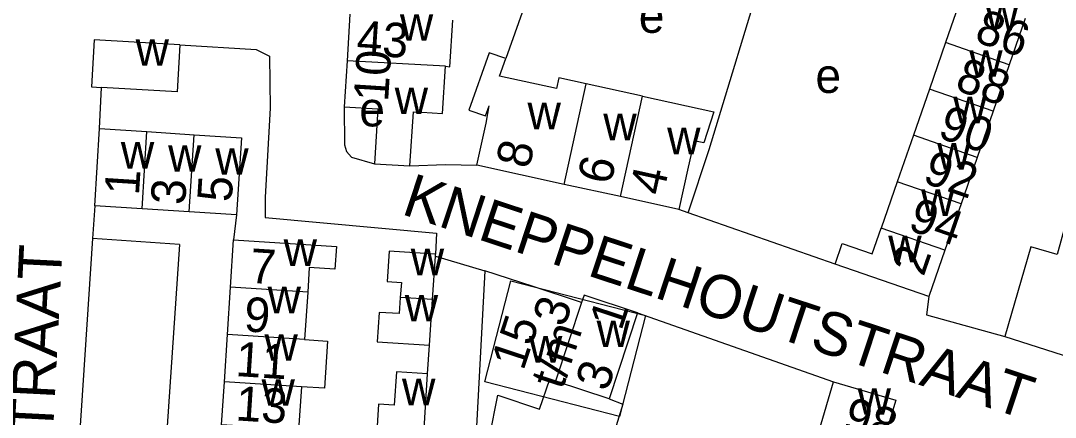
# Model space of a CAD drawing. Extents: x 159700 to 161346, y 381730 to 382922.
# Drawn here: x 160528.5 to 160648.4, y 382093.7 to 382139.7 of the extents above; entities that cross this region are included whole.
import ezdxf

# ---------------------------------------------------------------- set-up
doc = ezdxf.new("R2010")
doc.units = 0
for name, color, linetype in [('BLT_Basislijn', 7, 'Continuous'), ('BLT_Bebouwing', 7, 'Continuous'), ('BLT_Centroide', 7, 'Continuous'), ('BLT_Huisnummer', 7, 'Continuous'), ('BLT_Huisnummer_ tussenligend', 7, 'Continuous'), ('BLT_Huisnummer_zonder_bebouwing', 7, 'Continuous'), ('BLT_Onderverdeling_panden', 7, 'Continuous'), ('BLT_Plantopo', 7, 'Continuous'), ('BLT_Straatnaam', 7, 'Continuous')]:
    doc.layers.add(name, color=color, linetype=linetype)

msp = doc.modelspace()

# ---------------------------------------------------------------- linework, layer by layer
at = {"layer": 'BLT_Basislijn'}
for p, q in [((160591.41, 382154.25), (160584.69, 382135.26)), ((160537.62, 382127.15), (160537.83, 382131.93)), ((160537.05, 382118.21), (160536.8, 382114.41)), ((160605.81, 382117.41), (160604.74, 382117.78)), ((160622.85, 382111.45), (160605.81, 382117.41)), ((160553.47, 382117.17), (160553.15, 382114.28)), ((160536.8, 382114.41), (160535.16, 382089.9)), ((160546.87, 382113.74), (160536.8, 382114.41)), ((160546.87, 382113.74), (160545.23, 382089.23)), ((160576.53, 382112.36), (160582.26, 382110.69)), ((160599.95, 382105.8), (160622.66, 382097.82)), ((160642.5, 382103.07), (160651.59, 382100.14)), ((160575.62, 382098.75), (160575.85, 382102.04))]:
    msp.add_line(p, q, dxfattribs=at)
for points in [[(160681.91, 382220.18), (160679.43, 382214.59), (160683.36, 382212.77), (160677.31, 382195.82), (160674.59, 382196.42), (160665.51, 382171.9), (160668.53, 382170.99), (160661.57, 382151.91), (160658.85, 382152.82), (160649.77, 382125.87), (160651.89, 382124.66), (160648.56, 382112.55), (160645.53, 382113.46), (160642.5, 382103.07)], [(160605.81, 382117.41), (160608.25, 382124.72), (160614.86, 382146.46)], [(160546.92, 382136.85), (160555.77, 382136.31), (160557.32, 382135.53), (160557.37, 382129.52), (160556.8, 382119.22), (160556.8, 382116.86), (160576.67, 382115.05), (160576.54, 382112.62)], [(160565.95, 382129.69), (160566.01, 382125.26), (160566.22, 382124.5), (160566.8, 382123.83), (160569.46, 382123.09)], [(160573.57, 382122.83), (160577.69, 382122.99), (160581.33, 382122.91)], [(160633.7, 382107.69), (160633.43, 382105.59), (160642.5, 382103.07)], [(160596.66, 382095.83), (160598.24, 382095.24), (160592.76, 382077.43)]]:
    msp.add_lwpolyline(points, dxfattribs=at)
at = {"layer": 'BLT_Bebouwing'}
for p, q in [((160637.49, 382142.49), (160635.63, 382137.12)), ((160566.63, 382140.42), (160566.29, 382135.02)), ((160644.87, 382139.93), (160643.01, 382134.56)), ((160635.63, 382137.12), (160633.77, 382131.74)), ((160566.29, 382135.02), (160565.95, 382129.69)), ((160643.01, 382134.56), (160641.15, 382129.19)), ((160641.15, 382129.19), (160639.29, 382123.81)), ((160537.05, 382118.21), (160537.62, 382127.15)), ((160537.62, 382127.15), (160543.1, 382126.8)), ((160543.1, 382126.8), (160548.57, 382126.45)), ((160639.29, 382123.81), (160637.43, 382118.44)), ((160569.46, 382123.09), (160573.57, 382122.83)), ((160591.44, 382120.69), (160581.33, 382122.91)), ((160630.05, 382120.99), (160628.18, 382115.62)), ((160597.96, 382119.27), (160591.44, 382120.69)), ((160604.74, 382117.78), (160597.96, 382119.27)), ((160542.53, 382117.86), (160537.05, 382118.21)), ((160548, 382117.51), (160542.53, 382117.86)), ((160553.47, 382117.17), (160548, 382117.51)), ((160637.43, 382118.44), (160635.56, 382113.06)), ((160552.79, 382108.79), (160553.15, 382114.28)), ((160576.53, 382112.36), (160576.54, 382112.62)), ((160635.56, 382113.06), (160633.7, 382107.69)), ((160576.2, 382107.34), (160576.53, 382112.36)), ((160633.7, 382107.69), (160622.85, 382111.45)), ((160587.86, 382108.84), (160582.26, 382110.69)), ((160552.43, 382103.3), (160552.79, 382108.79)), ((160561.73, 382108.2), (160561.37, 382102.71)), ((160593.47, 382106.99), (160587.86, 382108.84)), ((160575.85, 382102.04), (160576.2, 382107.34)), ((160552.07, 382097.8), (160552.43, 382103.3)), ((160575.14, 382091.07), (160575.62, 382098.75)), ((160561.01, 382097.22), (160560.68, 382092.24)), ((160590.46, 382097.87), (160589.77, 382098.1)), ((160596.66, 382095.83), (160590.46, 382097.87)), ((160621.03, 382092.28), (160622.66, 382097.82))]:
    msp.add_line(p, q, dxfattribs=at)
for points in [[(160577.68, 382134.39), (160578.19, 382134.3), (160578.54, 382139.7)], [(160546.92, 382136.85), (160536.99, 382137.45), (160536.66, 382132), (160537.83, 382131.93)], [(160546.92, 382136.85), (160546.59, 382131.4), (160537.83, 382131.93)], [(160584.69, 382135.26), (160582.76, 382135.95), (160580.41, 382129.3), (160582.34, 382128.62), (160582.76, 382129.8)], [(160573.57, 382122.83), (160573.97, 382129.11), (160574.96, 382129.05), (160577.33, 382128.89), (160577.68, 382134.39)], [(160593.99, 382132.33), (160590.83, 382133.03), (160590.55, 382131.79), (160583.97, 382133.22), (160584.69, 382135.26)], [(160600.54, 382130.91), (160593.99, 382132.33)], [(160633.77, 382131.74), (160631.92, 382126.41)], [(160600.54, 382130.91), (160608.79, 382129.1), (160607.63, 382125.49), (160606.49, 382125.74), (160606.3, 382124.87), (160605.81, 382122.67), (160604.74, 382117.78)], [(160565.95, 382129.69), (160569.87, 382129.44), (160569.46, 382123.09)], [(160581.33, 382122.91), (160582.4, 382127.79), (160582.76, 382129.8)], [(160548.57, 382126.45), (160554.04, 382126.1), (160553.47, 382117.17)], [(160631.92, 382126.41), (160630.05, 382120.99)], [(160622.85, 382111.45), (160623.67, 382113.83), (160627.15, 382112.63), (160628.18, 382115.62)], [(160553.15, 382114.28), (160562.08, 382113.69), (160565.06, 382113.5), (160564.89, 382110.86), (160561.91, 382111.06), (160561.73, 382108.2)], [(160576.54, 382112.62), (160571.16, 382112.97), (160570.92, 382109.42), (160572.58, 382109.31), (160572.46, 382107.57)], [(160582.26, 382110.69), (160581.26, 382091.9), (160582.79, 382091.39), (160583.76, 382096.25), (160588.6, 382094.66), (160589.77, 382098.1)], [(160599.95, 382105.8), (160593.75, 382107.85), (160593.47, 382106.99)], [(160572.46, 382107.57), (160572.34, 382105.71), (160570, 382105.86), (160569.77, 382102.44), (160575.85, 382102.04)], [(160599.95, 382105.8), (160597.74, 382099.11), (160596.66, 382095.83)], [(160561.37, 382102.71), (160564.04, 382102.54), (160563.66, 382097.06), (160561.01, 382097.22)], [(160575.62, 382098.75), (160572, 382098.98), (160571.76, 382095.11), (160569.93, 382095.23), (160569.69, 382091.45), (160573.01, 382091.24)], [(160553.01, 382092.74), (160551.75, 382092.82), (160552.07, 382097.8)], [(160622.66, 382097.82), (160629.86, 382095.69), (160628.23, 382090.15)]]:
    msp.add_lwpolyline(points, dxfattribs=at)
at = {"layer": 'BLT_Onderverdeling_panden'}
for p, q in [((160643.01, 382134.56), (160635.63, 382137.12)), ((160577.68, 382134.39), (160566.29, 382135.02)), ((160591.44, 382120.69), (160593.99, 382132.33)), ((160641.15, 382129.19), (160633.77, 382131.74)), ((160597.96, 382119.27), (160600.54, 382130.91)), ((160542.53, 382117.86), (160543.1, 382126.8)), ((160548, 382117.51), (160548.57, 382126.45)), ((160639.29, 382123.81), (160631.92, 382126.41)), ((160637.43, 382118.44), (160630.05, 382120.99)), ((160635.56, 382113.06), (160628.18, 382115.62)), ((160561.73, 382108.2), (160552.79, 382108.79)), ((160576.2, 382107.34), (160572.46, 382107.57)), ((160593.47, 382106.99), (160590.46, 382097.87)), ((160561.37, 382102.71), (160552.43, 382103.3)), ((160561.01, 382097.22), (160552.07, 382097.8))]:
    msp.add_line(p, q, dxfattribs=at)
at = {"layer": 'BLT_Plantopo'}
msp.add_lwpolyline([(160585.25, 382109.53), (160600.87, 382105.51), (160597.86, 382093.8), (160582.24, 382097.81)], close=True, dxfattribs=at)

# ---------------------------------------------------------------- texts
at = {"layer": 'BLT_Centroide'}
for s, p in [('e', (160600.09, 382138.25)), ('w', (160640.25, 382138.53)), ('w', (160572.41, 382137.34)), ('w', (160541.79, 382134.44)), ('w', (160638.38, 382133.16)), ('e', (160620.56, 382131.29)), ('w', (160571.81, 382128.83)), ('e', (160567.71, 382127.41)), ('w', (160636.52, 382127.78)), ('w', (160587.2, 382127.08)), ('w', (160595.98, 382125.8)), ('w', (160603.38, 382124.19)), ('w', (160540.08, 382122.52)), ('w', (160545.55, 382122.16)), ('w', (160551.02, 382121.8)), ('w', (160634.66, 382122.41)), ('w', (160632.8, 382117.03)), ('w', (160558.94, 382111.25)), ('w', (160629, 382111.66)), ('w', (160573.67, 382110.16)), ('w', (160557.08, 382105.75)), ('w', (160572.98, 382104.81)), ('w', (160595.2, 382101.84)), ('w', (160556.72, 382100.25)), ('w', (160587.36, 382100.03)), ('w', (160572.66, 382095.09)), ('w', (160556.38, 382095.03)), ('w', (160625.45, 382094))]:
    msp.add_text(s, height=4, dxfattribs=at).set_placement(p)
at = {"layer": 'BLT_Huisnummer'}
for s, rotation, p in [('43', 356.3472, (160567.32, 382135.71)), ('10', 86.353, (160571.04, 382130.2)), ('88', 340.8972, (160636.58, 382131.69)), ('8', 77.6509, (160587.4, 382122.39)), ('4', 77.6452, (160602.91, 382119.28)), ('1', 86.351, (160542.17, 382119.36)), ('5', 86.3442, (160552.91, 382118.58)), ('94', 340.8993, (160631.14, 382115.46)), ('7', 356.2668, (160554.94, 382109.29)), ('2', 70.8959, (160633.08, 382109.91)), ('3', 71.7396, (160591.5, 382104.03)), ('1', 71.7346, (160598.07, 382103.62)), ('11', 356.2664, (160553.3, 382098.49)), ('98', 343.5545, (160623.58, 382092.28))]:
    msp.add_text(s, height=4, rotation=rotation, dxfattribs=at).set_placement(p)
at = {"layer": 'BLT_Huisnummer_ tussenligend'}
for s, rotation, p in [('86', 340.8972, (160638.84, 382137.3)), ('90', 340.8972, (160634.59, 382126.17)), ('6', 77.6542, (160596.85, 382120.54)), ('92', 340.8924, (160632.84, 382120.95)), ('3', 86.351, (160547.52, 382118.24)), ('9', 356.2668, (160554.28, 382103.67)), ('13', 356.2664, (160553.3, 382093.35))]:
    msp.add_text(s, height=4, rotation=rotation, dxfattribs=at).set_placement(p)
at = {"layer": 'BLT_Huisnummer_zonder_bebouwing'}
for s, p in [('15', (160586.72, 382099)), ('t/m', (160591.26, 382096.8)), ('3', (160596.46, 382096.58))]:
    msp.add_text(s, height=4, rotation=71.7396, dxfattribs=at).set_placement(p)
at = {"layer": 'BLT_Straatnaam'}
for s, height, rotation, p in [('KNEPPELHOUTSTRAAT', 5, 341.7431, (160572.46, 382117.29)), ('SCHEIDINGSTRAAT', 4.9999, 87.1045, (160530.11, 382050.11))]:
    msp.add_text(s, height=height, rotation=rotation, dxfattribs=at).set_placement(p)

doc.saveas('drawing.dxf')
